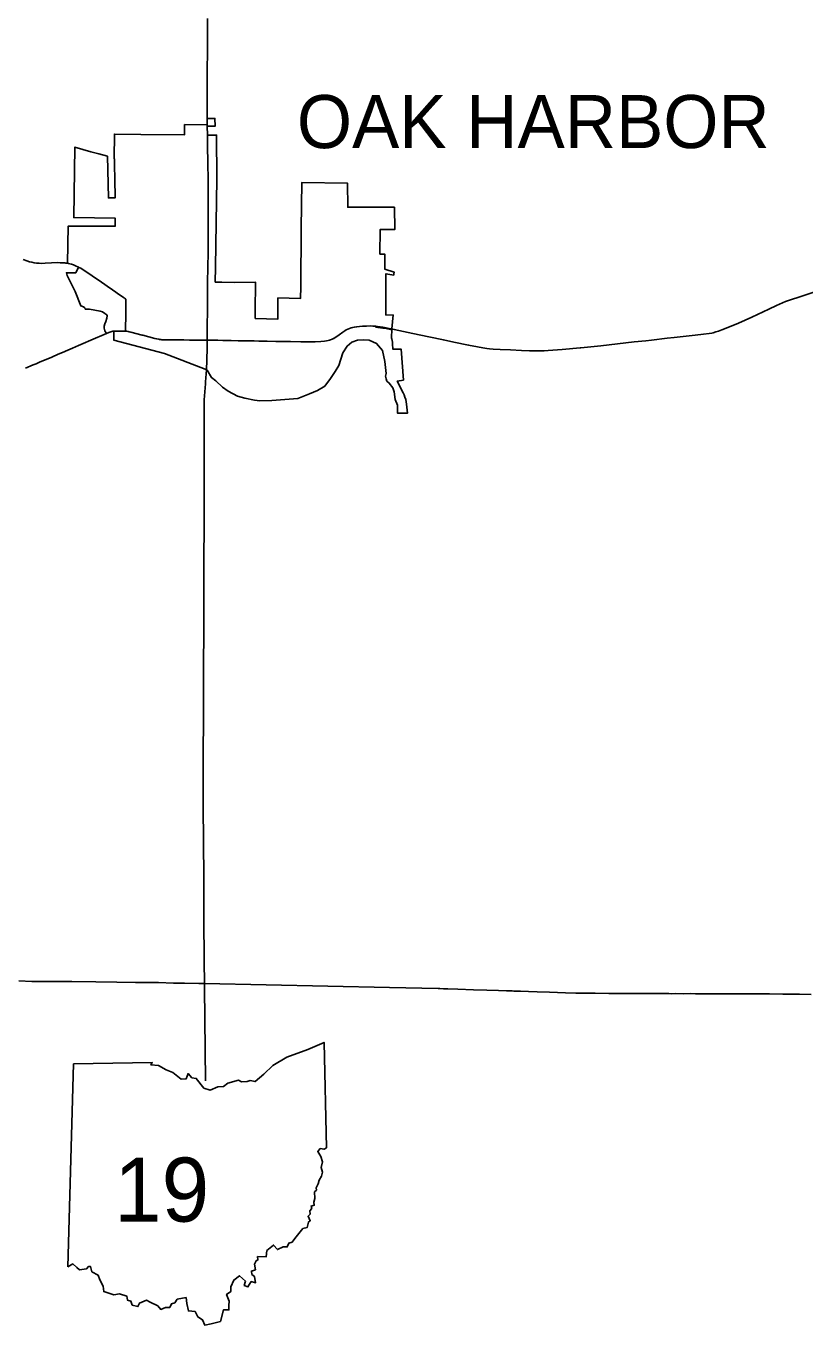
# Model space of a CAD drawing. Extents: x -82 to 873, y 0 to 440.
# Drawn here: x 264.9 to 319.9, y 100.3 to 192.1 of the extents above; entities that cross this region are included whole.
import ezdxf

# ---------------------------------------------------------------- set-up
doc = ezdxf.new("R2010")
doc.units = 0
for name, color, linetype in [('DV_X_Corp_Line', 7, 'Continuous'), ('GM_X_Corporation_Text', 7, 'Continuous'), ('GM_X_County', 7, 'Continuous'), ('GM_X_Interstate_Route', 7, 'Continuous'), ('PV_P_Text', 7, 'Continuous')]:
    doc.layers.add(name, color=color, linetype=linetype)

msp = doc.modelspace()

# ---------------------------------------------------------------- linework, layer by layer
at = {"layer": 'DV_X_Corp_Line'}
msp.add_lwpolyline([(289.65, 170.88), (289.646, 170.811), (289.779, 170.797), (290.138, 170.741), (290.369, 170.71), (290.771, 170.633), (290.75, 170.115), (290.752, 170.071), (290.757, 170.039), (290.764, 169.993), (290.788, 169.873), (290.813, 169.746), (290.826, 169.63), (290.835, 169.268), (291.447, 169.257), (291.599, 167.068), (291.161, 167.001), (291.584, 166.182), (291.647, 166.022), (291.697, 165.87), (291.754, 165.705), (291.793, 165.543), (291.823, 165.365), (291.893, 164.744), (291.168, 164.734), (291.168, 164.997), (291.165, 165.293), (291.002, 165.705), (290.94, 166.252), (290.844, 166.524), (290.588, 166.86), (290.422, 167.001), (290.37, 167.166), (290.317, 167.355), (290.37, 167.543), (290.287, 168.379), (290.106, 169.162), (289.699, 169.659), (289.172, 169.885), (288.78, 169.915), (288.358, 169.885), (287.952, 169.765), (287.605, 169.479), (287.319, 168.996), (287.168, 168.56), (287.018, 168.093), (286.762, 167.671), (286.445, 167.174), (286.039, 166.646), (285.511, 166.345), (284.954, 166.104), (284.139, 165.779), (282.287, 165.638), (281.44, 165.601), (281.074, 165.657), (280.373, 165.786), (279.863, 165.943), (279.203, 166.282), (278.798, 166.569), (278.329, 167.023), (278.019, 167.255), (277.705, 167.767), (277.658, 167.8), (277.582, 167.85), (274.699, 168.951), (271.106, 169.898), (271.112, 170.538), (271.062, 170.531), (271.031, 170.525), (270.994, 170.516), (270.961, 170.505), (270.904, 170.486), (270.753, 170.431), (270.592, 170.367), (270.476, 170.551), (270.437, 170.746), (270.43, 170.891), (270.47, 171.049), (270.545, 171.218), (270.621, 171.446), (270.651, 171.627), (270.618, 171.677), (270.479, 171.783), (270.301, 171.888), (270.152, 171.948), (269.395, 172.076), (269.091, 172.099), (269.051, 172.183), (268.978, 172.262), (268.769, 172.318), (268.375, 173.344), (267.806, 174.465), (267.766, 174.668), (268.42, 174.663), (268.61, 175.057), (268.397, 175.158), (268.257, 175.215), (268.127, 175.258), (268.01, 175.292), (267.918, 175.313), (267.838, 175.329), (267.887, 177.962), (271.222, 177.957), (271.212, 177.972), (271.204, 177.988), (271.2, 178.008), (271.2, 178.027), (271.205, 178.523), (268.28, 178.569), (268.366, 183.543), (269.491, 183.221), (270.045, 183.063), (270.661, 182.895), (270.736, 179.953), (271.201, 179.959), (271.187, 181.3), (271.17, 182.249), (271.157, 182.667), (271.154, 182.692), (271.15, 182.709), (271.144, 182.722), (271.136, 182.735), (271.158, 184.47), (273.022, 184.449), (276.118, 184.424), (276.12, 185.14), (277.721, 185.122), (277.72, 185.481), (277.718, 185.58), (278.261, 185.571), (278.274, 185.022), (277.723, 185.024), (277.73, 184.39), (278.384, 184.398), (278.391, 181.303), (278.308, 175.064), (278.29, 174.006), (278.756, 173.999), (279.68, 173.983), (281.129, 174), (281.101, 171.913), (281.111, 171.43), (282.724, 171.387), (282.714, 172.879), (284.32, 172.847), (284.332, 173.675), (284.365, 177.79), (284.42, 181.046), (287.639, 181.009), (287.658, 179.29), (290.959, 179.295), (290.977, 177.713), (289.96, 177.725), (289.93, 175.978), (290.279, 175.978), (290.279, 174.927), (290.929, 174.707), (290.912, 174.583), (290.909, 174.497), (290.355, 174.59), (290.355, 171.668), (290.859, 171.678), (290.774, 170.687), (290.585, 170.723), (290.377, 170.763), (290.135, 170.807), (289.77, 170.866)], close=True, dxfattribs=at)
at = {"layer": 'GM_X_County'}
msp.add_lwpolyline([(264.387, 124.587), (265.32, 124.557), (266.387, 124.546), (268.152, 124.545), (269.835, 124.532), (271.32, 124.507), (272.65, 124.484), (273.398, 124.471), (274.264, 124.464), (275.33, 124.44), (276.109, 124.427), (277.125, 124.406), (277.526, 124.396), (290.603, 124.129), (294.047, 124.042), (294.087, 124.043), (294.164, 124.041), (294.436, 124.027), (294.741, 124.017), (295.438, 123.998), (296.551, 123.967), (297.491, 123.943), (298.312, 123.91), (298.896, 123.892), (298.987, 123.889), (299.082, 123.885), (299.138, 123.881), (299.186, 123.88), (299.282, 123.877), (299.41, 123.869), (299.871, 123.856), (300.445, 123.839), (301.062, 123.822), (301.921, 123.792), (303.068, 123.754), (303.795, 123.732), (303.911, 123.725), (304.048, 123.724), (304.671, 123.713), (305.163, 123.712), (306.126, 123.707), (306.927, 123.703), (308.816, 123.691), (309.676, 123.688), (310.372, 123.686), (310.549, 123.685), (310.833, 123.688), (311.388, 123.685), (311.91, 123.687), (312.262, 123.683), (313.004, 123.683), (313.54, 123.679), (314.192, 123.681), (314.893, 123.674), (315.652, 123.67), (316.247, 123.669), (317.203, 123.67), (317.477, 123.668), (318.43, 123.652), (319.125, 123.645), (319.599, 123.64), (320.437, 123.634)], dxfattribs=at)
at = {"layer": 'GM_X_Interstate_Route'}
for points in [[(277.718, 185.58), (277.714, 187.496), (277.716, 188.477), (277.732, 190.829), (277.735, 190.98), (277.737, 191.126), (277.733, 191.529), (277.742, 192.637)], [(277.721, 185.118), (277.721, 185.122), (277.72, 185.481), (277.718, 185.58)], [(277.734, 184.112), (277.73, 184.39), (277.723, 185.024), (277.722, 185.05), (277.721, 185.118)], [(277.766, 182.137), (277.761, 182.548), (277.742, 183.515), (277.734, 184.112)], [(277.777, 181.211), (277.775, 181.514), (277.766, 182.137)], [(277.726, 170.927), (277.735, 171.958), (277.741, 172.904), (277.741, 172.987), (277.749, 174.022), (277.766, 175.017), (277.766, 175.054), (277.775, 176.085), (277.784, 177.135), (277.792, 177.848), (277.789, 179.096), (277.778, 180.379), (277.778, 180.934), (277.777, 181.211)], [(264.695, 175.603), (264.96, 175.504), (265.156, 175.444), (265.315, 175.405), (265.476, 175.373), (265.638, 175.35), (265.843, 175.333), (266.006, 175.326), (266.255, 175.332), (266.71, 175.355), (267.115, 175.376), (267.322, 175.374), (267.488, 175.371), (267.653, 175.359), (267.723, 175.35), (267.779, 175.34), (267.838, 175.329), (267.896, 175.317)], [(304.096, 169.345), (304.151, 169.351), (305.55, 169.5), (307.915, 169.767), (308.732, 169.858), (309.139, 169.903), (310.241, 170.028), (310.746, 170.084), (312.24, 170.248), (312.811, 170.314), (313.218, 170.367), (313.419, 170.402), (313.499, 170.419), (313.696, 170.474), (313.89, 170.537), (314.121, 170.623), (314.538, 170.794), (315.283, 171.105), (316.237, 171.518), (317.441, 172.079), (317.985, 172.336), (318.616, 172.632), (329.206, 176.101)], [(267.896, 175.317), (267.918, 175.313), (268.01, 175.292), (268.127, 175.258), (268.257, 175.215), (268.397, 175.158), (268.61, 175.057), (268.636, 175.044)], [(268.636, 175.044), (268.769, 174.982), (268.943, 174.873), (269.418, 174.555), (269.582, 174.445), (269.892, 174.235), (270.068, 174.113), (270.633, 173.723), (271.012, 173.463), (271.113, 173.392), (271.164, 173.356)], [(271.164, 173.356), (271.35, 173.227), (271.793, 172.922), (271.84, 172.89), (271.902, 172.849), (271.942, 172.818), (271.971, 172.795)], [(271.971, 172.795), (271.969, 172.632), (271.961, 172.02), (271.956, 171.684), (271.947, 170.666), (271.949, 170.531)], [(277.723, 169.893), (277.726, 170.927)], [(284.338, 169.781), (284.408, 169.78), (284.736, 169.772), (285.022, 169.772), (285.35, 169.784), (285.759, 169.807), (286.018, 169.825), (286.147, 169.844), (286.266, 169.868), (286.374, 169.898), (286.447, 169.924), (286.554, 169.969), (286.649, 170.016), (286.664, 170.023), (286.77, 170.083), (286.874, 170.149), (287.041, 170.267), (287.305, 170.463), (287.441, 170.555), (287.548, 170.618), (287.659, 170.673), (287.774, 170.72), (287.891, 170.759), (288.01, 170.792), (288.131, 170.818), (288.294, 170.846), (288.498, 170.87), (288.703, 170.886), (288.99, 170.897), (289.278, 170.9), (289.442, 170.896), (289.481, 170.894), (289.606, 170.885), (289.65, 170.88), (289.77, 170.866), (290.135, 170.807), (290.377, 170.763), (290.585, 170.723), (290.774, 170.687), (290.8, 170.681)], [(268.195, 169.326), (268.61, 169.507), (269.811, 170.039), (270.262, 170.235), (270.592, 170.367), (270.592, 170.367)], [(270.592, 170.367), (270.753, 170.431), (270.904, 170.486), (270.961, 170.505), (270.994, 170.516), (271.031, 170.525), (271.062, 170.531), (271.112, 170.538), (271.117, 170.539)], [(271.117, 170.539), (271.141, 170.542), (271.189, 170.542), (271.266, 170.541), (271.529, 170.537), (271.949, 170.531)], [(271.949, 170.531), (272.035, 170.521), (272.121, 170.506), (272.207, 170.485), (272.321, 170.456), (273.119, 170.25), (273.158, 170.239)], [(273.158, 170.239), (274.024, 170.015), (274.146, 169.986), (274.304, 169.955), (274.335, 169.949), (274.348, 169.947)], [(274.348, 169.947), (274.368, 169.943), (274.436, 169.936), (274.519, 169.93), (274.589, 169.928), (274.695, 169.925), (275.391, 169.915), (276.069, 169.908), (276.461, 169.904), (277.723, 169.893)], [(290.8, 170.681), (290.848, 170.671), (290.943, 170.652), (292.26, 170.377), (293.383, 170.135), (294.427, 169.913), (295.151, 169.763), (296.203, 169.552), (296.841, 169.424), (297.204, 169.357), (297.488, 169.313), (297.691, 169.289), (297.936, 169.268), (298.427, 169.239), (299.166, 169.208), (299.945, 169.176), (300.519, 169.151), (300.97, 169.139), (301.298, 169.137), (301.544, 169.144), (301.83, 169.161), (302.813, 169.234), (304.096, 169.345)], [(264.874, 167.911), (265.401, 168.14), (265.619, 168.232), (265.855, 168.331), (266.724, 168.699), (267.176, 168.894), (267.479, 169.021), (267.857, 169.18), (268.195, 169.326)], [(277.658, 167.807), (277.687, 168.473), (277.716, 169.35)], [(277.716, 169.35), (277.723, 169.893)], [(277.723, 169.893), (278.461, 169.885), (278.817, 169.878), (278.913, 169.876), (279.406, 169.868), (279.919, 169.858), (280.884, 169.84), (281.04, 169.838), (281.369, 169.832), (281.618, 169.829), (281.7, 169.828)], [(281.7, 169.828), (281.956, 169.823), (282.562, 169.811), (283.171, 169.803), (283.603, 169.793), (284.338, 169.781)], [(277.597, 166.951), (277.658, 167.8), (277.658, 167.807)], [(277.506, 160.434), (277.506, 160.866), (277.51, 161.808), (277.505, 162.968), (277.505, 163.453), (277.497, 164.809), (277.494, 165.384), (277.51, 165.678), (277.588, 166.816), (277.597, 166.951)], [(277.601, 117.518), (277.505, 126.289), (277.487, 128.711), (277.483, 129.86), (277.475, 131.035), (277.471, 131.666), (277.452, 134.662), (277.443, 136.715), (277.443, 137.637), (277.443, 139.342), (277.443, 140.952), (277.443, 141.066), (277.452, 142.707), (277.461, 143.816), (277.462, 144.288), (277.464, 145.622), (277.465, 146.935), (277.471, 149.234), (277.47, 150.63), (277.471, 150.92), (277.477, 152.394), (277.476, 153.913), (277.503, 157.238), (277.505, 159.003), (277.506, 160.434)]]:
    msp.add_lwpolyline(points, dxfattribs=at)
at = {"layer": 'PV_P_Text'}
msp.add_line((267.853, 104.361), (268.254, 118.724), dxfattribs=at)
msp.add_line((267.853, 104.361), (268.254, 118.724), dxfattribs=at)
for points in [[(268.254, 118.724), (273.827, 118.818), (273.74, 118.644), (274.266, 118.608), (274.824, 118.301), (275.296, 118.107), (275.874, 117.651), (276.22, 117.656), (276.366, 118.03), (276.631, 117.741), (276.945, 117.69), (277.488, 117.002), (277.937, 116.854), (278.474, 117.089), (278.875, 117.128), (279.169, 117.361), (279.934, 117.56), (280.147, 117.441), (280.552, 117.465), (280.755, 117.553), (281.109, 117.474), (281.73, 117.997), (282.37, 118.613), (283.354, 119.194), (284.824, 119.744), (285.986, 120.237), (286.155, 112.783)], [(268.254, 118.724), (273.827, 118.818), (273.74, 118.644), (274.266, 118.608), (274.824, 118.301), (275.296, 118.107), (275.874, 117.651), (276.22, 117.656), (276.366, 118.03), (276.631, 117.741), (276.945, 117.69), (277.488, 117.002), (277.937, 116.854), (278.474, 117.089), (278.875, 117.128), (279.169, 117.361), (279.934, 117.56), (280.147, 117.441), (280.552, 117.465), (280.755, 117.553), (281.109, 117.474), (281.73, 117.997), (282.37, 118.613), (283.354, 119.194), (284.824, 119.744), (285.986, 120.237), (286.155, 112.783)], [(286.155, 112.783), (285.984, 112.679), (285.716, 112.728), (285.537, 112.519), (285.759, 112.17), (285.864, 111.801), (285.771, 111.395), (285.863, 111.06), (285.8, 110.78), (285.633, 110.501), (285.575, 110.235), (285.432, 109.955), (285.444, 109.798), (285.308, 109.673), (285.333, 109.207), (285.264, 108.949), (285.287, 108.726), (285.067, 108.668), (285.117, 108.484), (284.977, 108.341), (285.007, 108.096), (284.848, 107.941), (285.003, 107.628), (284.878, 107.529), (284.776, 107.148), (284.492, 107.071), (283.926, 106.375), (283.726, 106.113), (283.501, 106.047), (283.377, 105.777), (283.101, 105.776), (282.682, 105.589), (282.412, 105.911), (281.938, 105.523), (281.883, 105.075), (281.283, 105.089), (281.307, 104.863), (281.173, 104.797), (281.051, 104.57), (281.122, 104.167), (280.841, 104.064), (280.875, 103.83), (281.055, 103.687), (281.135, 103.24), (280.837, 103.331), (280.592, 102.954), (280.341, 103.042), (280.424, 103.361), (279.999, 103.745), (279.597, 103.438), (279.388, 102.946), (279.385, 102.616), (279.086, 102.416), (279.278, 101.949), (279.243, 101.627), (279.249, 101.322), (278.875, 101.332), (278.648, 100.508)], [(286.155, 112.783), (285.984, 112.679), (285.716, 112.728), (285.537, 112.519), (285.759, 112.17), (285.864, 111.801), (285.771, 111.395), (285.863, 111.06), (285.8, 110.78), (285.633, 110.501), (285.575, 110.235), (285.432, 109.955), (285.444, 109.798), (285.308, 109.673), (285.333, 109.207), (285.264, 108.949), (285.287, 108.726), (285.067, 108.668), (285.117, 108.484), (284.977, 108.341), (285.007, 108.096), (284.848, 107.941), (285.003, 107.628), (284.878, 107.529), (284.776, 107.148), (284.492, 107.071), (283.926, 106.375), (283.726, 106.113), (283.501, 106.047), (283.377, 105.777), (283.101, 105.776), (282.682, 105.589), (282.412, 105.911), (281.938, 105.523), (281.883, 105.075), (281.283, 105.089), (281.307, 104.863), (281.173, 104.797), (281.051, 104.57), (281.122, 104.167), (280.841, 104.064), (280.875, 103.83), (281.055, 103.687), (281.135, 103.24), (280.837, 103.331), (280.592, 102.954), (280.341, 103.042), (280.424, 103.361), (279.999, 103.745), (279.597, 103.438), (279.388, 102.946), (279.385, 102.616), (279.086, 102.416), (279.278, 101.949), (279.243, 101.627), (279.249, 101.322), (278.875, 101.332), (278.648, 100.508)], [(278.648, 100.508), (277.998, 100.35), (277.547, 100.255), (277.387, 100.63), (277.065, 100.828), (276.855, 101.205), (276.391, 101.256), (276.281, 101.774), (276.229, 102.194), (275.596, 102.09), (275.421, 101.833), (275.197, 101.764), (275.066, 101.505), (274.76, 101.484), (274.431, 101.362), (274.216, 101.615), (273.677, 101.87), (273.435, 102.002), (272.928, 101.798), (272.82, 101.556), (272.417, 101.662), (272.323, 101.932), (272.079, 102.013), (272.025, 102.299), (271.504, 102.451), (271.105, 102.391), (270.401, 102.621), (270.358, 102.997), (270.119, 103.456), (269.994, 103.774), (269.549, 104.018), (269.459, 104.396), (269.316, 104.385), (269.186, 104.231), (268.693, 104.161), (268.495, 104.315), (268.219, 104.58), (267.853, 104.361)], [(278.648, 100.508), (277.998, 100.35), (277.547, 100.255), (277.387, 100.63), (277.065, 100.828), (276.855, 101.205), (276.391, 101.256), (276.281, 101.774), (276.229, 102.194), (275.596, 102.09), (275.421, 101.833), (275.197, 101.764), (275.066, 101.505), (274.76, 101.484), (274.431, 101.362), (274.216, 101.615), (273.677, 101.87), (273.435, 102.002), (272.928, 101.798), (272.82, 101.556), (272.417, 101.662), (272.323, 101.932), (272.079, 102.013), (272.025, 102.299), (271.504, 102.451), (271.105, 102.391), (270.401, 102.621), (270.358, 102.997), (270.119, 103.456), (269.994, 103.774), (269.549, 104.018), (269.459, 104.396), (269.316, 104.385), (269.186, 104.231), (268.693, 104.161), (268.495, 104.315), (268.219, 104.58), (267.853, 104.361)]]:
    msp.add_lwpolyline(points, dxfattribs=at)

# ---------------------------------------------------------------- texts
at = {"layer": 'GM_X_Corporation_Text'}
msp.add_text('OAK HARBOR', height=3.75, rotation=0.00501, dxfattribs=at).set_placement((284.061, 183.476))
at = {"layer": 'PV_P_Text'}
msp.add_text('19', height=4.5281, rotation=0.005, dxfattribs=at).set_placement((271.126, 107.564))

doc.saveas('drawing.dxf')
